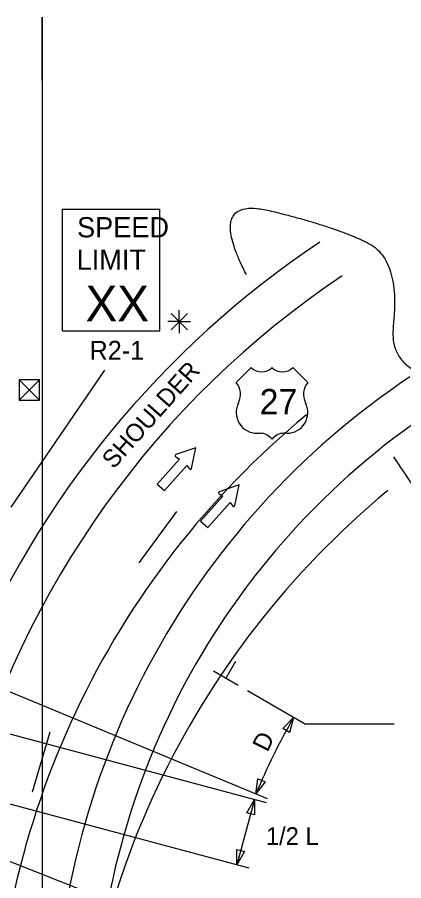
# Model space of a CAD drawing. Extents: x 16729 to 18464, y 5737 to 6974.
# Drawn here: x 16994.8 to 17147.3, y 6633.2 to 6974.1 of the extents above; entities that cross this region are included whole.
import ezdxf

# ---------------------------------------------------------------- set-up
doc = ezdxf.new("R2010")
doc.units = 0
for name, color, linetype in [('ALI_LEGAL_EX', 7, 'Continuous'), ('MT_SCRATCH_LEVEL_E', 7, 'Continuous'), ('PAVT_EDGE_EX', 7, 'Continuous'), ('TRAFFIC_SIGNS_PR', 7, 'Continuous'), ('TYPICAL_EX', 7, 'Continuous'), ('TYPICAL_TEXT_DIMEN_PR', 7, 'Continuous')]:
    doc.layers.add(name, color=color, linetype=linetype)

msp = doc.modelspace()

# ---------------------------------------------------------------- linework, layer by layer
at = {"layer": 'ALI_LEGAL_EX'}
for p, q in [((17004.68, 6974.12), (17004.68, 6155.98)), ((17004.68, 6891.53), (17004.68, 6027.61)), ((17007.7, 6691.9), (17000.71, 6668.24))]:
    msp.add_line(p, q, dxfattribs=at)
for points in [[(17004.68, 6949.12), (17004.68, 6974.12)], [(17043, 6758.79), (17057.75, 6778.98)]]:
    msp.add_lwpolyline(points, dxfattribs=at)
for centre in [(17325.51, 6555.03), (17357.65, 6525.15)]:
    msp.add_arc(centre, 340, 129.5666, 180, dxfattribs=at)
at = {"layer": 'MT_SCRATCH_LEVEL_E'}
for p, q in [((17065.34, 6804.16), (17057.46, 6801.48)), ((17063.63, 6795.99), (17065.34, 6804.16)), ((17058.9, 6799.7), (17050.1, 6789.79)), ((17057.36, 6800.64), (17058.9, 6799.7)), ((17052.89, 6787.3), (17061.7, 6797.21)), ((17061.7, 6797.21), (17062.82, 6795.8)), ((17050.1, 6789.79), (17052.89, 6787.3)), ((17082.42, 6789.5), (17074.54, 6786.82)), ((17080.72, 6781.33), (17082.42, 6789.5)), ((17075.99, 6785.04), (17067.18, 6775.13)), ((17074.45, 6785.99), (17075.99, 6785.04)), ((17069.98, 6772.65), (17078.78, 6782.56)), ((17078.78, 6782.56), (17079.9, 6781.14)), ((17067.18, 6775.13), (17069.98, 6772.65))]:
    msp.add_line(p, q, dxfattribs=at)
for centre, start, end in [((17057.61, 6801.04), 108.8028, 238.3418), ((17063.18, 6796.09), 218.4141, 348.1511), ((17074.7, 6786.38), 108.8028, 238.3418), ((17080.26, 6781.44), 218.4141, 348.1511)]:
    msp.add_arc(centre, 0.463, start, end, dxfattribs=at)
at = {"layer": 'PAVT_EDGE_EX'}
for radius, end in [(380, 157.5011), (364, 165.0045), (316, 180), (300, 180)]:
    msp.add_arc((17325.51, 6569.52), radius, 123.7854, end, dxfattribs=at)
at = {"layer": 'TRAFFIC_SIGNS_PR'}
for p, q in [((17012.67, 6898.36), (17051.07, 6898.36)), ((17012.67, 6850.36), (17012.67, 6898.36)), ((17051.07, 6850.36), (17051.07, 6898.36)), ((17012.67, 6850.36), (17051.07, 6850.36))]:
    msp.add_line(p, q, dxfattribs=at)
at = {"layer": 'TYPICAL_EX'}
for p, q in [((17081.21, 6829.94), (17087.1, 6835.84)), ((17109.51, 6829.94), (17103.61, 6835.84)), ((17089.45, 6809.88), (17090.63, 6809.88)), ((17101.26, 6809.88), (17100.08, 6809.88))]:
    msp.add_line(p, q, dxfattribs=at)
for centre, radius, start, end in [((17091.23, 6840.13), 5.96, 226.1404, 313.8596), ((17099.48, 6840.13), 5.96, 226.1404, 313.8596), ((17075.62, 6825.22), 7.31, 333.0977, 40.1936), ((17115.09, 6825.22), 7.31, 139.8064, 206.9023), ((17089.47, 6818.13), 8.24, 152.6698, 269.9013), ((17101.25, 6818.13), 8.24, 270.0987, 27.3302), ((17090.65, 6803.98), 5.91, 37.1038, 90.1385), ((17100.07, 6803.98), 5.91, 89.8615, 142.8962)]:
    msp.add_arc(centre, radius, start, end, dxfattribs=at)
at = {"layer": 'TYPICAL_TEXT_DIMEN_PR'}
for p, q in [((17061.96, 6857.16), (17055.58, 6850.78)), ((17055.59, 6857.16), (17061.96, 6850.78)), ((17058.77, 6853.97), (17058.77, 6858.43)), ((17058.77, 6853.97), (17054.24, 6853.97)), ((17058.77, 6853.97), (17061.96, 6853.97)), ((17058.77, 6853.97), (17063.25, 6853.97)), ((17058.77, 6853.97), (17058.77, 6849.47)), ((16992.47, 6780.68), (17029.33, 6834.75)), ((16995.58, 6831.02), (17003.58, 6823.02)), ((16995.58, 6823.02), (17003.58, 6831.02)), ((17077.17, 6713.12), (17081.06, 6719.86)), ((17082.04, 6710.31), (17072.29, 6715.93)), ((17093.61, 6665.56), (16977.03, 6713.85)), ((17108.22, 6695.16), (17085.71, 6708.17)), ((17099.6, 6693.37), (17103.89, 6697.66)), ((17103.89, 6697.66), (17102.32, 6691.8)), ((17108.22, 6695.16), (17143.57, 6695.16)), ((17093.19, 6664), (16981.21, 6693.99)), ((17100.96, 6692.59), (17099.6, 6693.37)), ((17102.32, 6691.8), (17100.96, 6692.59)), ((17088.99, 6667.48), (17089.79, 6673.49)), ((17092.69, 6672.29), (17088.99, 6667.48)), ((17089.79, 6673.49), (17091.24, 6672.89)), ((17091.24, 6672.89), (17092.69, 6672.29)), ((17086.29, 6638.21), (16982.82, 6665.93)), ((17088.41, 6665.28), (17081.5, 6639.5)), ((17085.37, 6660.03), (17088.41, 6665.28)), ((17088.41, 6665.28), (17088.41, 6659.21)), ((17086.89, 6659.62), (17085.37, 6660.03)), ((17088.41, 6659.21), (17086.89, 6659.62)), ((16964.45, 6651.69), (17046.11, 6619.48)), ((17081.5, 6639.5), (17081.5, 6645.57)), ((17081.5, 6645.57), (17083.02, 6645.16)), ((17084.53, 6644.75), (17081.5, 6639.5)), ((17083.02, 6645.16), (17084.53, 6644.75))]:
    msp.add_line(p, q, dxfattribs=at)
msp.add_lwpolyline([(16995.58, 6831.02), (16995.58, 6823.02), (17003.58, 6823.02), (17003.58, 6831.02)], close=True, dxfattribs=at)
msp.add_arc((17325.51, 6569.52), 256, 149.9625, 157.5013, dxfattribs=at)
for points in [[(17085.32, 6872.4), (17068.93, 6903.88), (17120.14, 6891.56), (17146.08, 6878.56), (17140.29, 6826.13), (17189.09, 6830.66)], [(17143.35, 6800.53), (17181.58, 6742.35), (17158.37, 6808.06), (17187.53, 6789.29)]]:
    msp.add_open_spline(points, degree=2, dxfattribs=at)

# ---------------------------------------------------------------- texts
at = {"layer": 'TRAFFIC_SIGNS_PR'}
for s, height, p in [('SPEED', 8, (17018.44, 6887.22)), ('LIMIT', 8, (17018.27, 6874.42)), ('XX', 14.031, (17021.78, 6854.12)), ('R2-1', 7.44, (17023.35, 6838.92))]:
    msp.add_text(s, height=height, dxfattribs=at).set_placement(p)
at = {"layer": 'TYPICAL_EX'}
msp.add_text('27', height=10, dxfattribs=at).set_placement((17090.47, 6817.37))
at = {"layer": 'TYPICAL_TEXT_DIMEN_PR'}
for s, rotation, p in [('SHOULDER', 48.378, (17032.86, 6795.46)), ('D', 63.7334, (17093.58, 6683.72))]:
    msp.add_text(s, height=7, rotation=rotation, dxfattribs=at).set_placement(p)
msp.add_text('1/2 L', height=7, dxfattribs=at).set_placement((17092.94, 6647.35))

doc.saveas('drawing.dxf')
